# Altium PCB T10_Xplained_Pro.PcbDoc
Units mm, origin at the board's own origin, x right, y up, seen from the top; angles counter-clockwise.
Board outline 71.5 x 89.25 mm, 2 copper layers (Top Layer, Bottom Layer), stack 0.325 mm thick; 61 components, 52 nets, 281 pads, 100 vias.
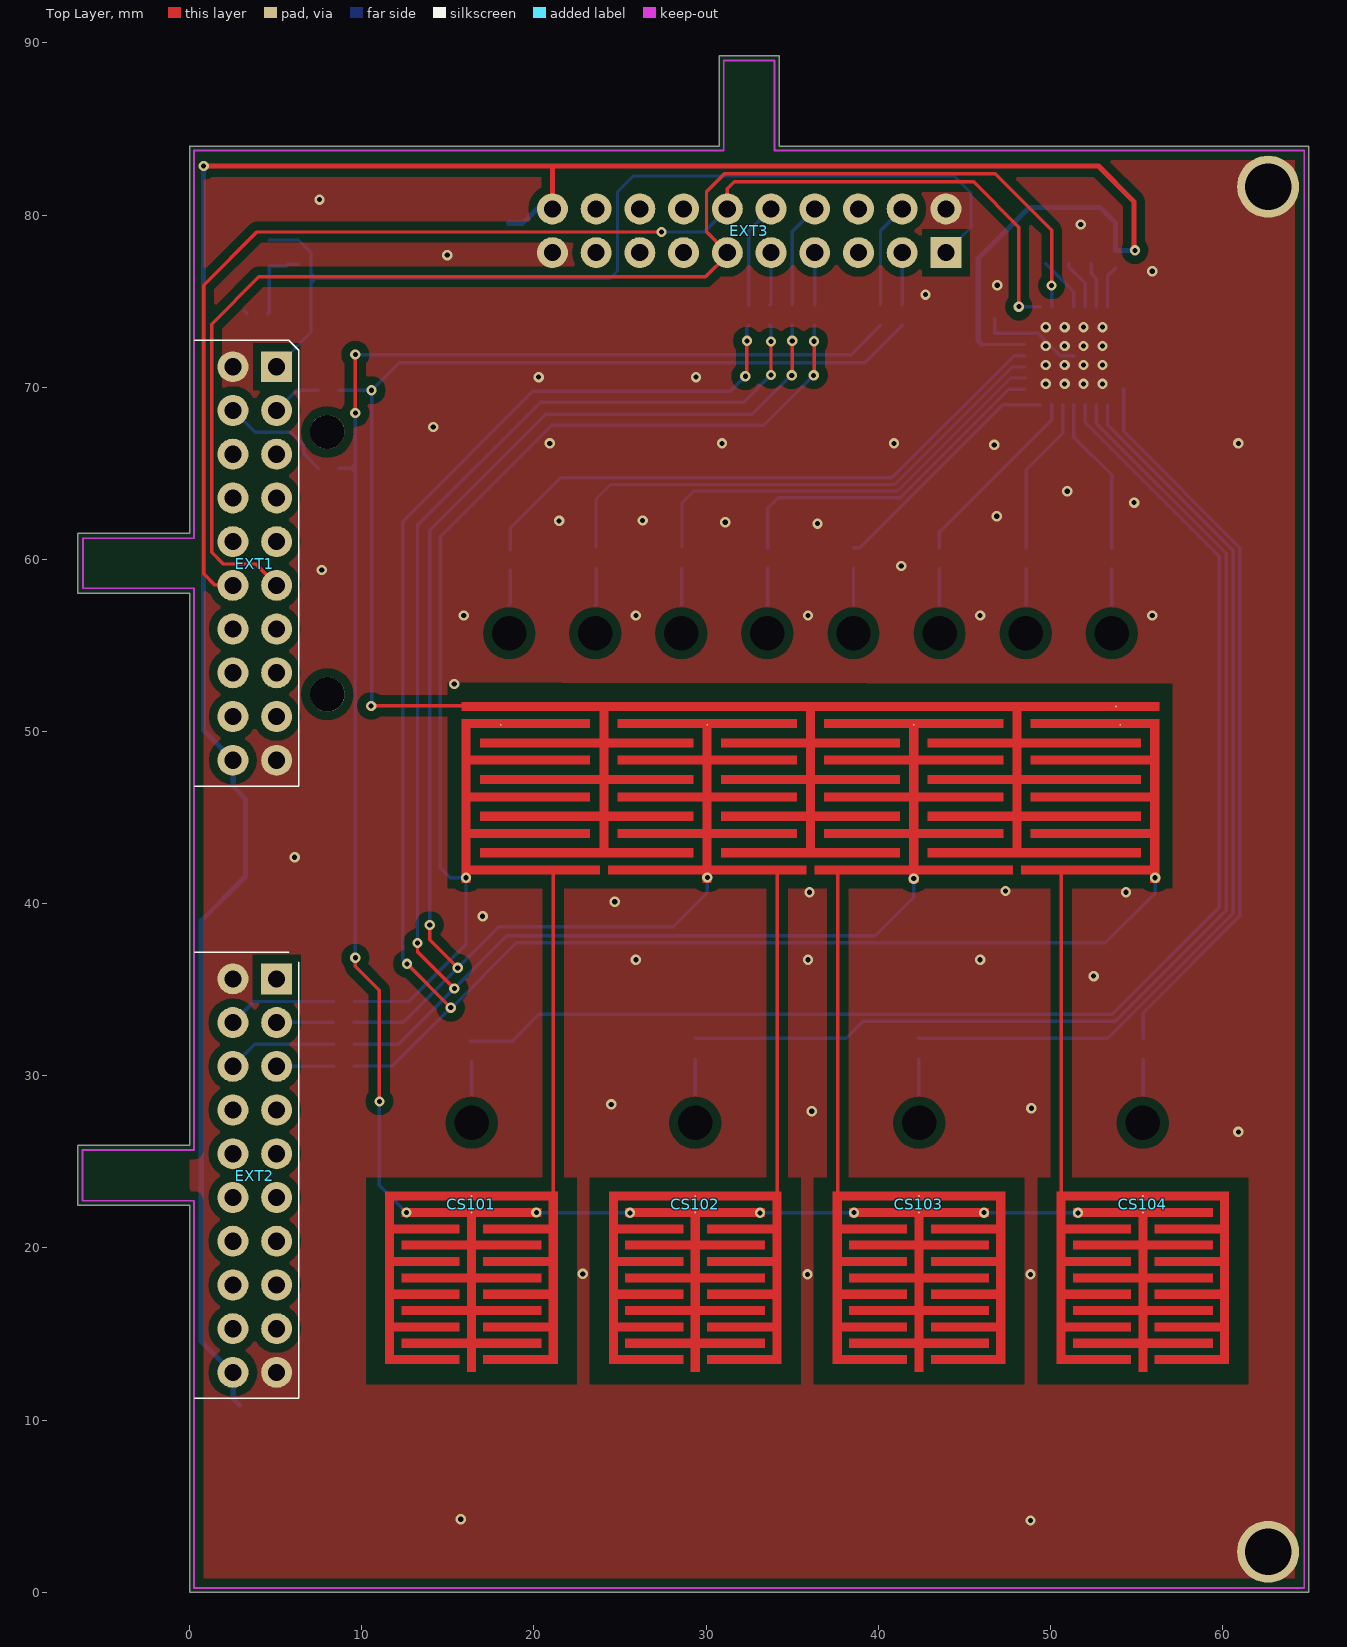
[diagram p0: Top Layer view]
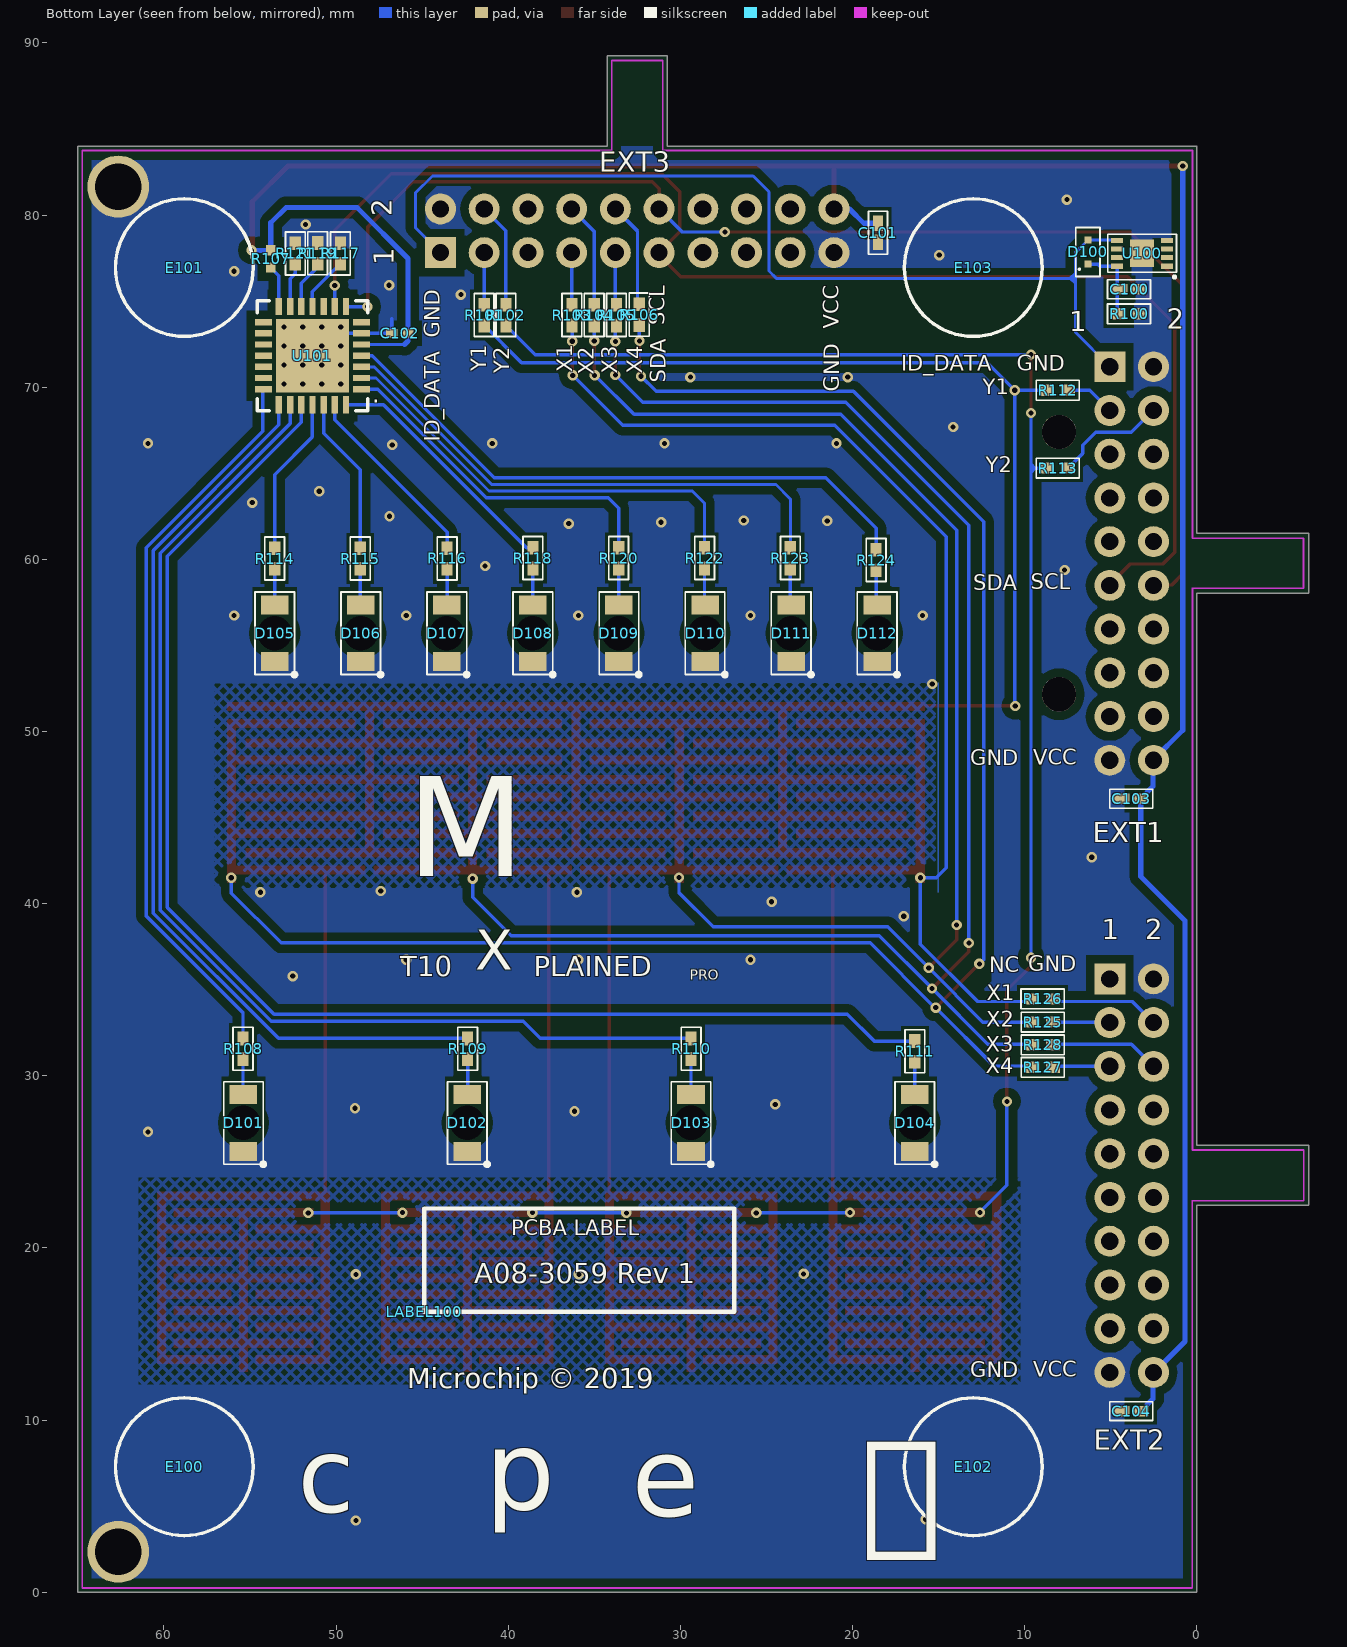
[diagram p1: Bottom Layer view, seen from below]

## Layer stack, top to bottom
Top Solder: solder mask 0.0102, Solder Resist, Dk 3.5
Top Layer: signal copper 0.0356
Dielectric 1: core 0.254, FR-4, Dk 4.2
Bottom Layer: signal copper 0.0356
Solder Side: solder mask 0.0102, Solder Resist, Dk 3.5

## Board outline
0,0 0,22.47 -6.5,22.47 -6.5,25.97 0,25.97 0,58.03 -6.5,58.03 -6.5,61.53 0,61.53 0.001,61.531 0.001,84.001 0,84 30.751,84 30.751,89.254 34.251,89.254 34.251,84 65,84 65,0

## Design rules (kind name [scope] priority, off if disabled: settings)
AcuteAngle [All] p1: minimum=8.50000000000000E+0001 checktracksonly=TRUE
AssemblyTestPointUsage [All] p1: allowmultiple=TRUE
AssemblyTestpoint [All] p1: testpointundercomponent=TRUE minsize=0.55 maxsize=2 preferedsize=0.8 minholesize=0 maxholesize=1 preferedholesize=0.25 testpointgrid=0.025 usegrid=FALSE gridtolerance=0 allowsidebottom=TRUE minspacing=1.27 compbodyclearance=0.127
Clearance Clearance_poly [InPolygon] p1: gap=0.5 ignorepadtopadclearanceinfootprint=FALSE except(0: Arc-Hole Track-Hole SMDPad-Hole THPad-Hole Via-Hole Fill-Hole Poly-Hole Region-Hole Text-Hole)
Clearance Clearance_LED [HasFootprint('AP4-00115')] p2: gap=0.05 ignorepadtopadclearanceinfootprint=FALSE except(0: Arc-Hole Track-Hole SMDPad-Hole THPad-Hole Via-Hole Fill-Hole Poly-Hole Region-Hole Text-Hole)
Clearance Clearance_1 [All] p3: gap=0.2 ignorepadtopadclearanceinfootprint=FALSE except(0: Arc-Hole Track-Hole SMDPad-Hole THPad-Hole Via-Hole Fill-Hole Poly-Hole Region-Hole Text-Hole)
ComponentClearance ComponentClearance_NoBOM [IsNoBOMComponent] p1: gap=0 collisioncheckmode=3 verticalgap=0 showdistances=FALSE
ComponentClearance [All] p2: gap=0.254 collisioncheckmode=3 verticalgap=0.254 showdistances=FALSE
DiffPairsRouting [All] p1: maxlimit=0.3 minlimit=0.15 mostfreqgap=0.2 toplayer_minwidth=0.381 toplayer_maxwidth=0.381 toplayer_prefwidth=0.381 bottomlayer_minwidth=0.381 bottomlayer_maxwidth=0.381 bottomlayer_prefwidth=0.381 maxuncoupledlength=20
FabricationTestPointUsage TestPointUsage [All] p1: valid=0 allowmultiple=TRUE
FabricationTestpoint Testpoint [All] p1: side=2 testpointundercomponent=TRUE minsize=0.55 maxsize=2 preferedsize=0.8 minholesize=0 maxholesize=1 preferedholesize=0.25 testpointgrid=0 allowsidebottom=TRUE usegrid=FALSE gridtolerance=0 minspacing=1.27 compbodyclearance=0.127
HoleSize [All] p1: absolutevalues=TRUE maxlimit=10 minlimit=0.2 maxpercent=80.000 minpercent=20.000
HoleToHoleClearance [All] p1: gap=0.45 allowstackedmicrovias=TRUE
MinimumAnnularRing [All] p1: minimumring=0.1
MinimumSolderMaskSliver [All] p1: minsoldermaskwidth=0.1
PasteMaskExpansion [All] p1: expansion=0.05
PlaneClearance [All] p1: clearance=0.3
PlaneConnect PlaneConnect_VIA [IsVia] p1: planeconnectstyle=Direct reliefexpansion=0.508 reliefentries=4 reliefconductorwidth=0.254 reliefairgap=0.254
PlaneConnect [All] p2: planeconnectstyle=Relief reliefexpansion=0.508 reliefentries=4 reliefconductorwidth=0.254 reliefairgap=0.254
PolygonConnect PolygonConnect_GND [HasPad('Free-666')] p1: connectstyle=Direct reliefconductorwidth=0.254 reliefentries=4 polygonreliefangle="90 Angle" airgapwidth=0.254
PolygonConnect PolygonConnect_VIA [IsVia] p2: connectstyle=Direct reliefconductorwidth=0.254 reliefentries=4 polygonreliefangle="90 Angle" airgapwidth=0.254
PolygonConnect [All] p3: connectstyle=Direct reliefconductorwidth=0.254 reliefentries=4 polygonreliefangle="90 Angle" airgapwidth=0.254
RoutingVias [All] p1: holewidth=0.3 width=0.6 viastyle="Through Hole" minholewidth=0.3 minwidth=0.6 maxholewidth=0.3 maxwidth=0.6
SMDNeckDown [All] p1: percent=70.000
SilkToSilkClearance SilkToSilkClearance_Text [IsText vs IsText] p1: silktosilkclearance=0
SilkToSilkClearance [All] p2: silktosilkclearance=0.01
SilkToSolderMaskClearance SilkscreenOverComponentPads [IsPad] p1: minsilkscreentomaskgap=0.1 clearancetoexposedcopper=TRUE
SolderMaskExpansion SolderMaskTenting [IsVia AND NOT (IsFabTestpoint OR IsAssyTestpoint)] p1: expansion=-1
SolderMaskExpansion [All] p2: expansion=0.05
ViasUnderSMD [All] p1: allowed=FALSE
Width [All] p1: maxlimit=0.3 minlimit=0.175 preferedwidth=0.2
16 further rules are at their usual default settings.

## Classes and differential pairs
component class T10_Xplained_Pro_TopLevel: E100 E101 E102 E103 FIXTURE100 LABEL100 PCB100 PCBADOC100 TEST100 TESTDOC100
component class T10_Xplained_Pro: C100 C101 C102 C103 C104 CS101 CS102 CS103 CS104 D100 D101 D102 D103 D104 D105 D106 D107 D108 D109 D110 D111 D112 EXT1 EXT2 EXT3 R100 R101 R102 R103 R104 R105 R106 R107 R108 R109 R110 R111 R112 R113 R114 R115 R116 R117 R118 R119 R120 R121 R122 R123 R124 R125 R126 R127 R128 U100 U101

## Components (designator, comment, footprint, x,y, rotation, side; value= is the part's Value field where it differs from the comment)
C100 "Recommended by Escatec. No datasheet available yet." AP1-00001 3.931,75.698 r180 bottom value=4.7uF
C101 "" AP1-00001 18.518,78.972 r270 bottom value=4.7uF
C102 "" AP1-00053 46.288,73.129 r0 bottom value=100n
C103 "" AP1-00001 3.8,46.095 r0 bottom value=4.7uF
C104 "" AP1-00001 3.8,10.52 r0 bottom value=4.7uF
CS101 "QMatrix Button 1" ? 16.368,18.261 r0 top
CS102 "QMatrix Button 1" ? 29.368,18.261 r0 top
CS103 "QMatrix Button 1" ? 42.368,18.261 r0 top
CS104 "QMatrix Button 1" ? 55.376,18.261 r0 top
D100 "Farnell# 1615809" AP4-00036 6.319,77.857 r90 bottom value=BAT54XV2T1G
D101 "LED_21" AP4-00115 55.376,27.261 r270 bottom value=LTST-C250KRKT
D102 "LED_21" AP4-00115 42.376,27.261 r270 bottom value=LTST-C250KRKT
D103 "LED_21" AP4-00115 29.376,27.261 r270 bottom value=LTST-C250KRKT
D104 "LED_21" AP4-00115 16.376,27.261 r270 bottom value=LTST-C250KRKT
D105 "LED_21" AP4-00115 53.562,55.707 r270 bottom value=LTST-C250KRKT
D106 "LED_21" AP4-00115 48.562,55.707 r270 bottom value=LTST-C250KRKT
D107 "LED_21" AP4-00115 43.562,55.707 r270 bottom value=LTST-C250KRKT
D108 "LED_21" AP4-00115 38.562,55.707 r270 bottom value=LTST-C250KRKT
D109 "LED_21" AP4-00115 33.562,55.707 r270 bottom value=LTST-C250KRKT
D110 "LED_21" AP4-00115 28.562,55.707 r270 bottom value=LTST-C250KRKT
D111 "LED_21" AP4-00115 23.562,55.707 r270 bottom value=LTST-C250KRKT
D112 "LED_21" AP4-00115 18.562,55.707 r270 bottom value=LTST-C250KRKT
E100 "" AP8-00192 58.811,7.29 r180 bottom value=SJ-5076
E101 "" AP8-00192 58.811,76.951 r180 bottom value=SJ-5076
E102 "" AP8-00192 12.979,7.29 r180 bottom value=SJ-5076
E103 "" AP8-00192 12.979,76.951 r180 bottom value=SJ-5076
EXT1 "" AP8-00621 3.78,59.76 r90 top locked value=TF201-2*10RGF-W2-NF
EXT2 "" AP8-00621 3.78,24.2 r90 top locked value=TF201-2*10RGF-W2-NF
EXT3 "" AP8-00621 32.501,79.089 r0 top value=TF201-2*10RGF-W2-NF
LABEL100 "" AP8-00317 44.87,16.293 r180 bottom value="Label PCBA"
R100 "R2" AP2-00000 3.931,74.265 r0 bottom value=100k
R101 "R2" AP2-00000 41.391,74.193 r270 bottom value=1k
R102 "R2" AP2-00000 40.132,74.193 r90 bottom value=1k
R103 "R2" AP2-00000 36.297,74.193 r270 bottom value=1k
R104 "R2" AP2-00000 35.001,74.193 r90 bottom value=1k
R105 "R2" AP2-00000 33.706,74.193 r270 bottom value=1k
R106 "R2" AP2-00000 32.385,74.219 r90 bottom value=1k
R107 "" AP2-00011 53.786,77.451 r90 bottom value=1k
R108 "R2" AP2-00000 55.402,31.573 r270 bottom value=330R
R109 "R2" AP2-00000 42.352,31.573 r270 bottom value=330R
R110 "R2" AP2-00000 29.376,31.573 r270 bottom value=330R
R111 "R2" AP2-00000 16.376,31.419 r270 bottom value=330R
R112 "R2" AP2-00000 8.077,69.825 r0 bottom value=1k
R113 "R2" AP2-00000 8.077,65.303 r180 bottom value=1k
R114 "R2" AP2-00000 53.562,60.05 r270 bottom value=330R
R115 "R2" AP2-00000 48.591,60.05 r270 bottom value=330R
R116 "R2" AP2-00000 43.547,60.052 r270 bottom value=330R
R117 "R2" AP2-00000 49.743,77.769 r270 bottom value=0R
R118 "R2" AP2-00000 38.562,60.077 r270 bottom value=330R
R119 "R2" AP2-00000 51.063,77.777 r270 bottom value=0R
R120 "R2" AP2-00000 33.577,60.077 r270 bottom value=330R
R121 "R2" AP2-00000 52.364,77.769 r270 bottom value=0R
R122 "R2" AP2-00000 28.592,60.077 r270 bottom value=330R
R123 "R2" AP2-00000 23.607,60.077 r270 bottom value=330R
R124 "R2" AP2-00000 18.622,59.962 r270 bottom value=330R
R125 "R2" AP2-00000 8.941,33.122 r0 bottom value=1k
R126 "R2" AP2-00000 8.95,34.468 r180 bottom value=1k
R127 "R2" AP2-00000 8.941,30.494 r0 bottom value=1k
R128 "R2" AP2-00000 8.941,31.801 r180 bottom value=1k
U100 "ATSHA204A-SWI" AP6-00409 3.169,77.781 r0 bottom value="ATSHA204 SWI UDFN8"
U101 "MCP23017-E_ML" AP6-00497 51.368,71.833 r0 bottom value=MCP23017

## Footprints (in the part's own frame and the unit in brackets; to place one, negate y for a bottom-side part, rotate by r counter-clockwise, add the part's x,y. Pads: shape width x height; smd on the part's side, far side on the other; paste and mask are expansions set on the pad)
AP1-00001 [mm] "Standard 0402 SMD capacitor footprint"
  rect 0.9x0.6 smd: 1(-0.55,0) 2(0.55,0)
  silkscreen extent -1.25,-0.55 1.25,0.55, body extent -0.5,-0.3 0.5,0.3, height 0.2
AP1-00053 [mm] "Chip Capacitor, 2-Leads, Body 1.0x0.5mm, IPC High Density"
  rect 0.65x0.5 smd: 1(-0.475,0) 2(0.475,0)
  body extent -0.5,-0.3 0.5,0.3, height 0.2
AP2-00000 [mm] "Standard 0402 SMD resistor footprint"
  rect 0.8x0.65 smd: 1(-0.6,0) 2(0.6,0)
  silkscreen extent -1.25,-0.58 1.25,0.58, body extent -0.5,-0.3 0.5,0.3, height 0.2
AP2-00011 [mm] "Chip Resistor, 2-Leads, Body 1,0x0,5mm, IPC High Density"
  rect 0.6x0.55 smd: 1(-0.5,0) 2(0.5,0)
  body extent -0.5,-0.3 0.5,0.3, height 0.2
AP4-00036 [mm] "Molded Diode, 2-Leads, Body 1,2x0,8mm, IPC Medium Density"
  rect 0.4x0.4 smd: 1(-0.7,0) 2(0.7,0)
  silkscreen extent -1.42,-0.7 1.43,0.7, body extent -0.8,-0.4 0.8,0.4, height 0.7
AP4-00115 [mm] "3.2x1.6mm, 1305, Reverse mount SMD LED"
  round 0 hole 2 unplated: 0(0,0)
  rect 1.1x1.6 smd: 1(-1.65,0) 2(1.65,0)
  silkscreen extent -2.4,-1.15 2.5,1.25, body extent -1.6,-0.8 1.6,0.8, height 0.29
AP6-00409 [mm]
  rect 0.7x0.3 smd mask-1: 1(-1.45,0.75) 2(-1.45,0.25) 3(-1.45,-0.25) 4(-1.45,-0.75) 5(1.45,-0.75) 6(1.45,-0.25) 7(1.45,0.25) 8(1.45,0.75)
  rect 1.4x1.6 smd paste-0.025 mask+0.075: 9(0,0)
  silkscreen extent -2,-1.1 2,1.45, body extent -1.55,-1.05 1.55,1.05, height 0.6
AP6-00497 [mm] "QFN, 28-Leads, Body 6x6mm (max), Pitch 0.65mm, IPC Medium Density"
  rect 1x0.37 smd: 1(-2.85,1.95) 2(-2.85,1.3) 3(-2.85,0.65) 4(-2.85,0) 5(-2.85,-0.65) 6(-2.85,-1.3) 7(-2.85,-1.95) 15(2.85,-1.95) 16(2.85,-1.3) 17(2.85,-0.65) 18(2.85,0) 19(2.85,0.65) 20(2.85,1.3) 21(2.85,1.95)
  rect 0.37x1 smd: 8(-1.95,-2.85) 9(-1.3,-2.85) 10(-0.65,-2.85) 11(0,-2.85) 12(0.65,-2.85) 13(1.3,-2.85) 14(1.95,-2.85) 22(1.95,2.85) 23(1.3,2.85) 24(0.65,2.85) 25(0,2.85) 26(-0.65,2.85) 27(-1.3,2.85) 28(-1.95,2.85)
  rect 4.25x4.25 smd: 29(0,0)
  silkscreen extent -3.2,-3.2 3.2,3.2, body extent -3,-3 3,3, height 1.02
AP8-00192 [mm]
  silkscreen extent -4,-4 4,4, body extent -4,-4 4,4, height 2.79
AP8-00317 [mm] "Placement area for 18x6mm sticker"
  silkscreen extent 0,0 18,6
AP8-00621 [mm] "2x5 Receptacle THM, Right Angle. No Guide. 2.54mm pitch. Length 13.2mm, width 5.0mm, height 5mm"
  rect 1.8x1.8 hole 1: 1(11.43,-1.27)
  round 1.8 hole 1: 2(11.43,1.27) 3(8.89,-1.27) 4(8.89,1.27) 5(6.35,-1.27) 6(6.35,1.27) 7(3.81,-1.27) 8(3.81,1.27) 9(1.27,-1.27) 10(1.27,1.27) 11(-1.27,-1.27) 12(-1.27,1.27) 13(-3.81,-1.27) 14(-3.81,1.27) 15(-6.35,-1.27) 16(-6.35,1.27) 17(-8.89,-1.27) 18(-8.89,1.27) 19(-11.43,-1.27) 20(-11.43,1.27)
  rect 2.1x2.1 on Top Paste: 19(-11.43,-1.27) 19(-11.43,1.27) 19(-8.89,-1.27) 19(-8.89,1.27) 19(-6.35,-1.27) 19(-6.35,1.27) 19(-3.81,-1.27) 19(-3.81,1.27) 19(-1.27,-1.27) 19(-1.27,1.27) 19(1.27,-1.27) 19(1.27,1.27) 19(3.81,-1.27) 19(3.81,1.27) 19(6.35,-1.27) 19(6.35,1.27) 19(8.89,-1.27) 19(8.89,1.27) 19(11.43,-1.27) 19(11.43,1.27)
  body extent -12.95,-1.47 12.95,11.3, height 4.98
? [mm]
  round 0.1 smd paste-0.05: X(0,4.75) Y(0,3.8)
  Top Layer region: -0.7,-5 -5,-5 -5,5 5,5 5,-5 0.7,-5 0.7,-4.5 4.5,-4.5 4.5,-3.1 0.7,-3.1 0.7,-2.6 4.5,-2.6 4.5,-1.2 0.7,-1.2 0.7,-0.7 4.5,-0.7 4.5,0.7 0.7,0.7 0.7,1.2 4.5,1.2 4.5,2.6 0.7,2.6 0.7,3.1 4.5,3.1 4.5,4.5 -4.5,4.5 -4.5,3.1 -0.7,3.1 -0.7,2.6 -4.5,2.6 -4.5,1.2 -0.7,1.2 -0.7,0.7 -4.5,0.7 -4.5,-0.7 -0.7,-0.7 -0.7,-1.2 -4.5,-1.2 -4.5,-2.6 -0.7,-2.6 -0.7,-3.1 -4.5,-3.1 -4.5,-4.5 -0.7,-4.5 -0.7,-5
  Top Layer region: -0.25,-5.45 -0.25,-4.05 -4.05,-4.05 -4.05,-3.55 -0.25,-3.55 -0.25,-2.15 -4.05,-2.15 -4.05,-1.65 -0.25,-1.65 -0.25,-0.25 -4.05,-0.25 -4.05,0.25 -0.25,0.25 -0.25,1.65 -4.05,1.65 -4.05,2.15 -0.25,2.15 -0.25,3.55 -4.05,3.55 -4.05,4.05 -0.25,4.05 0.25,4.05 4.05,4.05 4.05,3.55 0.25,3.55 0.25,2.15 4.05,2.15 4.05,1.65 0.25,1.65 0.25,0.25 4.05,0.25 4.05,-0.25 0.25,-0.25 0.25,-1.65 4.05,-1.65 4.05,-2.15 0.25,-2.15 0.25,-3.55 4.05,-3.55 4.05,-4.05 0.25,-4.05 0.25,-5.45 -0.25,-5.45

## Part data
C100 C101 C103 C104: library part A01-0347, "Ceramic capacitor, SMD 0402, X5R, 6.3V, +/-20% (de33687)", Manufacturer=Murata, MPN=GRM155R60J475ME87D, TemperatureRange="-55°C to +85°C", Tolerance=+-20%
C102: library part A01-0246, "Ceramic capacitor, SMD 0402, X7R, 16V, +/-10%", Manufacturer=Kemet, MPN=C0402C104K4RACTU, TemperatureRange="-55 - +125 deg C", Tolerance="16V, +/-10%"
CS101 CS102 CS103 CS104: library part QMatrixButton, "QMatrix Button"
D100: library part A04-0049, "Schottky diode, If:200mA, Vf:0.35V, Vrrm:30V, SOD-523", Manufacturer="ON Semiconductor", MPN=BAT54XV2T1G, TemperatureRange="-55°C to +125°C"
D101 D102 D103 D104 D105 D106 D107 D108 D109 D110 D111 D112: library part A10-0204, "LED, SMD, RED, 3.2x1.2mm, reverse mount"
E100 E101 E102 E103: library part A08-0053, "2.8mm adhesive feet,diam 8.0mm", Manufacturer=3M, MPN=SJ-5076
EXT1 EXT2 EXT3: library part A08-1512, "2x10, female pin header receptable, right-angled, 2.54mm pitch, THM, Pin In Paste", Manufacturer="Pro-data International Corp", MPN=F201-2*10RGF-W2-NF
LABEL100: library part A09-0611, "PCBA identification label PP Top White Gloss", Manufacturer="ACT Logimark AS", MPN=505462
R100: library part A02-0260, "Thick film resistor, SMD 0402, 1/16W, 1%", TemperatureRange="-55 - +125 deg C", Tolerance="1 %"
R101 R102 R103 R104 R105 R106 R107 R112 R113 R125 R126 R127 R128: library part A02-0212, "Thick film resistor, SMD 0402, 1/16W, 1%", TemperatureRange="-55 - +125 deg C", Tolerance="1 %"
R108 R109 R110 R111 R114 R115 R116 R118 R120 R122 R123 R124: library part A02-0200, "Thick film resistor, SMD 0402, 1/16W, 1%", Manufacturer=ASJ, MPN=CR10-3300-FK, TemperatureRange="-55 - +125 deg C", Tolerance="1 %"
R117 R119 R121: library part A02-0163, "RES 0.0 OHM 1/16W 0402 SMD", Manufacturer=(n/a), MPN=RMCF0402ZT0R00, TemperatureRange="-55 - +125 deg C", Tolerance="1 %"
U100: library part A06-1276, "ATSHA204 with 1-wire interface and UDFN8 package", Manufacturer=ATMEL, MPN=ATSHA204A-MAHCZ-T
U101: library part A06-1534, "16-Bit I/O Expander with I2C interface, 28-Lead QFN", Manufacturer="Microchip Technology Inc", MPN=MCP23017-E/ML, TemperatureRange="-40°C to +125°C"

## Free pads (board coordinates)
  round 2 hole 2 unplated: 2(8,67.4) 3(8,52.16)
  round 3.6 hole 2.7 paste-2.6: 666(62.65,2.35) 666(62.65,81.65)
  round 0.1 smd paste-0.05: x1(18.062,50.397) x2(30.062,50.397) x3(42.062,50.397) x4(54.062,50.397) Y(53.812,51.457)

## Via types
v1: diameter 0.6, hole 0.3, Top Layer to Bottom Layer, 70 vias
v2: diameter 0.6, hole 0.3, Top Layer to Bottom Layer, tented both sides, 30 vias

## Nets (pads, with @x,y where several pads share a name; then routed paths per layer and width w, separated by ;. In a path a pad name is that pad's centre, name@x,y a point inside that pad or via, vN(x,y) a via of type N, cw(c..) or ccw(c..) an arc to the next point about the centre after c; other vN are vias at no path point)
GND: C100.2 C101.2 C102.2 C103.2 C104.2 D101.2 D102.2 D103.2 D104.2 D105.2 D106.2 D107.2 D108.2 D109.2 D110.2 D111.2 D112.2 EXT1.2 EXT1.19@5.05,48.33 EXT2.2 EXT2.19@5.05,12.77 EXT3.2 EXT3.19@21.071,77.819 pad.666 R100.1 R117.1 R119.1 R121.1 U100.4 U100.9 U101.6 U101.29 | length 6.2
  Bottom Layer w0.2: R100.1@3.169,74.427 R100.1 ; C102.2 46.763,73.988
  Bottom Layer w0.203: C102.2 48.514,73.129 U101.6 49.28,73.133 50.58,71.833 U101.29
  other v1: 48.844,4.166 15.748,4.242 35.89,18.466 48.844,18.466 22.835,18.491 36.14,27.94 48.895,28.118 24.486,28.341 52.512,35.789 17.018,39.271 24.695,40.107 36.008,40.665 54.393,40.665 47.396,40.74 6.096,42.697 15.367,52.756 7.671,59.385 41.337,59.614 36.474,62.078 31.115,62.154 21.463,62.234 26.314,62.255 46.888,62.509 54.866,63.297 50.978,63.955 46.736,66.65 14.148,67.691 20.269,70.587 29.413,70.587 42.748,75.381 46.915,75.921 14.961,77.673 51.765,79.451 7.544,80.899
  other v2: 60.92,26.74 25.92,36.74 35.92,36.74 45.92,36.74 15.92,56.74 25.92,56.74 35.92,56.74 45.92,56.74 55.92,56.74 20.92,66.74 30.92,66.74 40.92,66.74 60.92,66.74 49.728,70.193 50.828,70.193 51.928,70.193 53.028,70.193 49.728,71.293 50.828,71.293 51.928,71.293 53.028,71.293 49.728,72.393 50.828,72.393 51.928,72.393 53.028,72.393 49.728,73.493 50.828,73.493 51.928,73.493 53.028,73.493 55.92,76.74
ID_DATA: D100.2 EXT1.1 EXT3.1 U100.5 | length 59.3
  Bottom Layer w0.175: U100.5 4.632,78.544 6.306,78.544 D100.2 7.034,77.841 7.034,76.633 ; EXT1.1@5.07,71.21 7.034,73.174 7.034,76.026 ; 7.034,76.407 7.112,76.329 7.338,76.329 ; 7.186,76.178 7.186,76.333 7.26,76.407 ; EXT3.1 45.39,79.277 45.39,81.28 44.398,82.272 25.767,82.272 24.847,81.352 24.847,76.752 24.424,76.329 7.338,76.329 ; 7.034,76.026 7.338,76.329 ; 7.034,76.026 7.034,76.633 ; 7.034,76.633 7.338,76.329
NetC100_1: C100.1 D100.1 R100.2 U100.8 | length 4.6
  Bottom Layer w0.2: R100.2 4.619,74.353 U100.8 5.619,77.031 5.745,77.157 D100.1
NetD101_1: D101.1 R108.2 | length 2.1
  Bottom Layer w0.2: D101.1@55.402,28.911 R108.2
NetD102_1: D102.1 R109.2 | length 2.1
  Bottom Layer w0.2: D102.1@42.352,28.911 R109.2
NetD103_1: D103.1 R110.2 | length 2.1
  Bottom Layer w0.2: D103.1 R110.2
NetD104_1: D104.1 R111.2 | length 1.9
  Bottom Layer w0.2: D104.1 R111.2
NetD105_1: D105.1 R114.2 | length 2.1
  Bottom Layer w0.2: D105.1 R114.2
NetD106_1: D106.1 R115.2 | length 2.1
  Bottom Layer w0.2: D106.1 48.591,57.386 R115.2
NetD107_1: D107.1 R116.2 | length 2.1
  Bottom Layer w0.2: R116.2 43.547,57.372 D107.1
NetD108_1: D108.1 R118.2 | length 2.1
  Bottom Layer w0.2: D108.1 R118.2
NetD109_1: D109.1 R120.2 | length 2.1
  Bottom Layer w0.2: D109.1 33.577,57.372 R120.2
NetD110_1: D110.1 R122.2 | length 2.1
  Bottom Layer w0.2: D110.1 28.592,57.387 R122.2
NetD111_1: D111.1 R123.2 | length 2.1
  Bottom Layer w0.2: D111.1 23.607,57.402 R123.2
NetD112_1: D112.1 R124.2 | length 2
  Bottom Layer w0.2: D112.1 18.622,57.417 R124.2
NetEXT1_3: EXT1.3 R112.1 | length 2.9
  Bottom Layer w0.2: EXT1.3@5.07,68.67 6.225,69.825 R112.1
NetEXT1_4: EXT1.4 R113.2 | length 6.6
  Bottom Layer w0.2: EXT1.4@2.53,68.67 3.814,67.386 5.867,67.386 6.629,66.624 6.629,66.151 R113.2
NetEXT2_3: EXT2.3 R125.1 | length 3.8
  Top Layer w0.2: EXT2.3@5.07,33.11 EXT2.3@5.585,33.11
  Bottom Layer w0.2: EXT2.3@5.07,33.11 5.082,33.122 R125.1
NetEXT2_4: EXT2.4 R126.2 | length 6.3
  Bottom Layer w0.2: EXT2.4@2.53,33.11 3.735,34.315 R126.2@8.366,34.315
NetEXT2_5: EXT2.5 R127.1 | length 4.5
  Top Layer w0.2: EXT2.5@5.07,30.57 EXT2.5@5.792,30.57
  Bottom Layer w0.2: EXT2.5@5.578,30.57 5.07,30.57 5.084,30.556 R127.1@8.366,30.556
NetEXT2_6: EXT2.6 R128.2 | length 6.4
  Bottom Layer w0.2: EXT2.6@2.53,30.57 3.786,31.826 R128.2@8.366,31.826
NetEXT3_3: EXT3.3 R101.1 | length 3
  Bottom Layer w0.2: R101.1 EXT3.3
NetEXT3_4: EXT3.4 R102.2 | length 6.1
  Bottom Layer w0.2: R102.2 40.132,79.1 EXT3.4
NetEXT3_7: EXT3.7 R103.1 | length 3.6
  Top Layer w0.2: EXT3.7 36.462,77.669 36.347,77.554 EXT3.7@36.468,77.432
  Bottom Layer w0.2: R103.1 36.311,74.808 EXT3.7
NetEXT3_8: EXT3.8 R104.2 | length 6.1
  Bottom Layer w0.2: R104.2 35.001,79.049 EXT3.8
NetEXT3_9: EXT3.9 R105.1 | length 3.1
  Bottom Layer w0.2: R105.1 33.771,74.859 EXT3.9
NetEXT3_10: EXT3.10 R106.2 | length 6.1
  Bottom Layer w0.2: R106.2@32.487,74.768 32.487,79.074 EXT3.10
NetR107_1: R107.1 U101.14 | length 2.5
  Bottom Layer w0.2: U101.14 53.318,76.483 R107.1
NetR108_1: R108.1 U101.21 | length 42.9
  Bottom Layer w0.2: U101.21 54.254,69.919 54.254,67.438 61.012,60.681 61.012,39.281 55.402,33.671 R108.1
NetR109_1: R109.1 U101.22 | length 53.9
  Bottom Layer w0.2: R109.1@42.312,32.173 53.338,32.173 60.612,39.446 60.612,60.515 53.318,67.808 U101.22
NetR110_1: R110.1 U101.23 | length 66.4
  Bottom Layer w0.2: R110.1 38.138,32.173 39.132,33.167 53.767,33.167 60.212,39.612 60.212,60.349 52.668,67.893 U101.23
NetR111_1: R111.1 U101.24 | length 79.2
  Bottom Layer w0.2: R111.1@16.286,32.019 18.741,32.019 20.289,33.567 53.601,33.567 59.812,39.778 59.812,60.184 52.018,67.977 U101.24
NetR117_2: R117.2 U101.11 | length 3.2
  Bottom Layer w0.2: R117.2 51.368,75.544 U101.11
NetR119_2: R119.2 U101.12 | length 2.9
  Bottom Layer w0.2: R119.2 51.063,76.985 52.018,76.03 U101.12
NetR121_2: R121.2 U101.13 | length 2.6
  Bottom Layer w0.2: R121.2 52.364,76.605 52.668,76.3 U101.13
SCL: EXT1.12 EXT3.12 U101.8 | length 76.2
  Top Layer w0.2: EXT1.12@2.53,58.51 1.458,58.51 0.812,59.157 0.812,75.936 3.895,79.019 v1(27.409,79.019) ; EXT3.12 31.231,81.527 31.632,81.927 45.547,81.927 48.168,79.305 v1(48.168,74.682)
  Bottom Layer w0.2: v1(27.409,79.019) 29.891,79.019 EXT3.12 ; v1(48.168,74.682) 48.17,74.683 U101.8
SDA: EXT1.11 EXT3.11 U101.9 | length 79.9
  Top Layer w0.2: EXT1.11@5.07,58.51 3.848,59.732 1.962,59.732 1.272,60.422 1.272,73.656 4.022,76.407 29.966,76.407 31.231,77.672 EXT3.11 30.022,79.029 30.022,81.352 31.067,82.397 46.801,82.397 50.068,79.13 v1(50.068,75.91)
  Bottom Layer w0.2: U101.9 v1(50.068,75.91)
SLIDER_1: R124.1 U101.4 | length 35.3
  Bottom Layer w0.2: R124.1 18.622,61.802 21.552,64.732 40.797,64.732 47.899,71.833 U101.4
SLIDER_2: R123.1 U101.3 | length 30.9
  Bottom Layer w0.175: R123.1 23.607,63.51 24.441,64.344 40.958,64.344 47.797,71.183 U101.3
SLIDER_3: R122.1 U101.2 | length 25.5
  Bottom Layer w0.175: R122.1 28.592,63.263 29.298,63.969 41.113,63.969 47.677,70.533 U101.2
SLIDER_4: R120.1 U101.1 | length 20.1
  Bottom Layer w0.2: R120.1 33.577,62.964 34.194,63.582 41.274,63.582 47.575,69.883 U101.1
SLIDER_5: R118.1 U101.28 | length 14.3
  Bottom Layer w0.2: R118.1 38.934,60.677 47.241,68.983 U101.28
SLIDER_6: R116.1 U101.27 | length 11
  Bottom Layer w0.2: R116.1 43.547,61.582 50.068,68.103 U101.27
SLIDER_7: R115.1 U101.26 | length 9.2
  Bottom Layer w0.2: R115.1 48.591,65.198 50.718,67.325 U101.26
SLIDER_8: R114.1 U101.25 | length 9.2
  Bottom Layer w0.2: U101.25 51.368,67.11 53.562,64.916 R114.1
VCC_TARGET: C101.1 C102.1 C103.1 C104.1 EXT1.20 EXT2.20 EXT3.20 R107.2 U101.5 | length 158
  Top Layer w0.3: v1(0.811,82.847) 52.791,82.847 54.862,80.777 54.862,78.001 v1(54.911,77.951) ; EXT3.20 21.071,82.847
  Bottom Layer w0.2: 46.024,72.483 U101.5
  Bottom Layer w0.3: v1(0.811,82.847) 0.811,50.069 2.53,48.35 2.53,46.815 C103.1 3.25,41.585 0.672,39.007 0.672,14.561 2.443,12.79 2.53,12.79 2.53,11.24 2.882,10.888 ; C101.1 19.337,79.522 20.174,80.359 EXT3.20 ; 46.024,72.483 45.813,72.694 C102.1 45.813,77.478 48.767,80.432 52.907,80.432 53.786,79.552 R107.2 v1(54.911,77.951)
X_1: CS101.X pad.x1 R103.2 R126.1 | length 80.4
  Top Layer w0.2: 21.057,22.809 21.133,22.885 21.133,41.986 ; v1@36.246,72.644 v1(36.271,72.669) ; v1@36.271,70.688 v1@36.271,72.644
  Bottom Layer w0.2: R126.1@9.566,34.315 12.725,34.315 16.053,37.643 v1(16.053,41.504) 15.137,41.504 14.554,42.087 14.554,61.314 21.033,67.793 33.35,67.793 v1(36.246,70.688) ; v1(36.271,72.669) 36.271,73.538 36.311,73.579 R103.2
X_2: CS102.X pad.x2 R104.1 R125.2 | length 97.3
  Top Layer w0.2: v1(13.945,38.76) 13.945,37.897 v1(15.57,36.271) ; 34.138,22.987 34.138,41.935 ; v1@34.9,70.637 v1@35.052,70.79 ; v1@35.001,70.79 v1(35.001,72.694)
  Bottom Layer w0.2: R125.2 12.421,33.122 v1(15.57,36.271) 17.958,38.659 28.092,38.659 30.074,40.64 v1(30.074,41.517) ; v1(13.945,38.76) 13.945,61.697 20.676,68.428 32.69,68.428 v1@34.9,70.637 ; R104.1 35.001,72.745 v1@35.052,72.694
  other v1: 34.976,70.688
X_3: CS103.X pad.x3 R105.2 R128.1 | length 111
  Top Layer w0.2: v1(13.233,37.719) 13.233,37.211 v1(15.375,35.07) ; v1(33.771,70.714) v1(33.771,72.659) ; 37.643,41.957 37.643,23.086 37.718,23.011 ; 47.092,42.037 47.117,42.012
  Bottom Layer w0.2: R128.1@9.566,31.826 12.131,31.826 v1(15.375,35.07) 18.43,38.125 39.827,38.125 42.062,40.361 v1(42.062,41.453) ; v1(13.233,37.719) 13.233,61.976 20.383,69.126 32.184,69.126 v1(33.771,70.714) ; R105.2 33.771,73.528 v1(33.771,72.659)
X_4: CS104.X pad.x4 R106.1 R127.2 | length 126.4
  Top Layer w0.2: v1(12.624,36.5) v1(15.164,33.96) ; v1(32.283,70.637) 32.372,70.726 v1(32.372,72.695) ; 50.622,22.936 50.622,41.957
  Bottom Layer w0.2: R127.2@9.541,30.57 11.774,30.57 v1(15.164,33.96) 15.215,33.96 18.974,37.719 53.188,37.719 56.083,40.615 v1(56.083,41.504) ; v1(12.624,36.5) 12.373,36.751 12.373,62.19 19.937,69.755 31.401,69.755 v1(32.283,70.637) ; v1(32.372,72.695) 32.372,73.453 R106.1@32.487,73.568
Y_1: pad.Y R101.2 R112.2 | length 58.6
  Top Layer w0.2: v1(10.541,51.486) 16.535,51.486
  Bottom Layer w0.2: R112.2 v1(10.566,69.825) ; v1(10.541,51.486) 10.566,51.511 v1(10.566,69.825) ; R101.2 39.223,71.425 12.167,71.425 v1(10.566,69.825)
Y_2: CS101.Y CS102.Y CS103.Y CS104.Y R102.1 R113.1 | length 100.3
  Top Layer w0.2: v1(9.627,36.855) 9.627,36.354 11.024,34.957 v1(11.024,28.51) ; v1(9.627,68.504) v1(9.627,71.898) ; 19.517,22.052 19.557,22.012
  Bottom Layer w0.2: R113.1 9.398,65.303 ; v1(9.627,36.855) 9.627,65.329 ; 9.627,65.075 9.398,65.303 ; 9.627,65.532 9.398,65.303 ; v1(9.627,68.504) 9.627,65.329 ; v1(9.627,71.898) 38.436,71.898 R102.1 ; v1(11.024,28.51) 11.024,23.63 v1(12.593,22.061) ; v1(20.142,22.061) 20.154,22.049 25.57,22.049 v1(25.582,22.037) ; v1(33.132,22.037) 33.138,22.043 38.586,22.043 v1(38.592,22.049) ; v1(46.142,22.049) 46.148,22.043 51.603,22.043 v1(51.609,22.037) ; 9.398,65.303 9.601,65.303 9.627,65.329
pads on no net: D101.0 D102.0 D103.0 D104.0 D105.0 D106.0 D107.0 D108.0 D109.0 D110.0 D111.0 D112.0 EXT1.5 EXT1.6 EXT1.7 EXT1.8 EXT1.9 EXT1.10 EXT1.13 EXT1.14 EXT1.15 EXT1.16 EXT1.17 EXT1.18 EXT1.19@2.51,48.33 EXT1.19@2.51,50.87 EXT1.19@2.51,53.41 EXT1.19@2.51,55.95 EXT1.19@2.51,58.49 EXT1.19@2.51,61.03 EXT1.19@2.51,63.57 EXT1.19@2.51,66.11 EXT1.19@2.51,68.65 EXT1.19@2.51,71.19 EXT1.19@5.05,48.33 EXT1.19@5.05,50.87 EXT1.19@5.05,53.41 EXT1.19@5.05,55.95 EXT1.19@5.05,58.49 EXT1.19@5.05,61.03 EXT1.19@5.05,63.57 EXT1.19@5.05,66.11 EXT1.19@5.05,68.65 EXT1.19@5.05,71.19 EXT2.1 EXT2.7 EXT2.8 EXT2.9 EXT2.10 EXT2.11 EXT2.12 EXT2.13 EXT2.14 EXT2.15 EXT2.16 EXT2.17 EXT2.18 EXT2.19@2.51,12.77 EXT2.19@2.51,15.31 EXT2.19@2.51,17.85 EXT2.19@2.51,20.39 EXT2.19@2.51,22.93 EXT2.19@2.51,25.47 EXT2.19@2.51,28.01 EXT2.19@2.51,30.55 EXT2.19@2.51,33.09 EXT2.19@2.51,35.63 EXT2.19@5.05,12.77 EXT2.19@5.05,15.31 EXT2.19@5.05,17.85 EXT2.19@5.05,20.39 EXT2.19@5.05,22.93 EXT2.19@5.05,25.47 EXT2.19@5.05,28.01 EXT2.19@5.05,30.55 EXT2.19@5.05,33.09 EXT2.19@5.05,35.63 EXT3.5 EXT3.6 EXT3.13 EXT3.14 EXT3.15 EXT3.16 EXT3.17 EXT3.18 EXT3.19@21.071,77.819 EXT3.19@21.071,80.359 EXT3.19@23.611,77.819 EXT3.19@23.611,80.359 EXT3.19@26.151,77.819 EXT3.19@26.151,80.359 EXT3.19@28.691,77.819 EXT3.19@28.691,80.359 EXT3.19@31.231,77.819 EXT3.19@31.231,80.359 EXT3.19@33.771,77.819 EXT3.19@33.771,80.359 EXT3.19@36.311,77.819 EXT3.19@36.311,80.359 EXT3.19@38.851,77.819 EXT3.19@38.851,80.359 EXT3.19@41.391,77.819 EXT3.19@41.391,80.359 EXT3.19@43.931,77.819 EXT3.19@43.931,80.359 U100.1 U100.2 U100.3 U100.6 U100.7 U101.7 U101.10 U101.15 U101.16 U101.17 U101.18 U101.19 U101.20

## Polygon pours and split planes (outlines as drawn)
GND on Bottom Layer "GND" (hatched 45Degree grid 0.5 track 0.2, remove dead copper, pour order 30): 10.248,24.084 10.248,12.07 61.499,12.07 61.468,12.101 61.468,24.084
GND on Bottom Layer "GND" (hatched 45Degree grid 0.5 track 0.2, pour order 28): 15.002,53.322 15.002,40.665 57.836,40.665 57.836,53.254
GND on Bottom Layer "GND" (hatched 45Degree grid 0.5 track 0.2, pour order 26): 15.002,52.837 15.011,52.827 15.011,40.665
GND on Bottom Layer "GND" (solid, remove dead copper, pour order 6): 0,0 65,0 65,84 0.001,84
GND on Top Layer "GND" (solid, remove dead copper, pour order 4): 0,0 65,0 65,84 0.001,84

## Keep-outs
Keep-Out Layer:
  lines w0.1: 64.732,0.24 0.252,0.24 0.252,22.743 0.25,22.745 -6.225,22.745 -6.225,25.695 0.25,25.695 ; 64.748,0.24 64.748,83.751 ; 0.25,25.695 0.25,25.695 ; 0.25,25.695 0.25,41.639 0.25,58.32 ; 0.25,58.32 0.25,58.32 ; 0.25,58.32 -6.2,58.32 -6.2,61.22 0.225,61.22 0.25,61.245 0.25,83.749 31.024,83.749 31.026,83.751 31.026,88.975 33.976,88.975 33.976,83.751 ; 33.976,83.751 49.92,83.751 64.748,83.751 ; 33.976,83.751 33.976,83.751 ; 64.748,83.751 64.748,83.751

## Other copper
Top Layer:
  pour cut-out: 10.248,24.084 10.248,12.603 10.248,12.07 10.781,12.07 22.491,12.07 22.491,24.008 22.491,24.084 22.415,24.084
  pour cut-out: 21.627,52.837 15.002,52.837 15.002,40.899 57.081,40.899 57.081,52.769
  pour cut-out: 23.248,24.084 23.248,12.603 23.248,12.07 23.781,12.07 35.491,12.07 35.491,24.008 35.491,24.084 35.415,24.084
  pour cut-out: 36.248,24.084 36.248,12.603 36.248,12.07 36.781,12.07 48.491,12.07 48.491,24.008 48.491,24.084 48.415,24.084
  pour cut-out: 49.256,24.084 49.256,12.603 49.256,12.07 49.79,12.07 61.499,12.07 61.499,24.008 61.499,24.084 61.423,24.084
  region net X_1: 15.812,41.207 16.312,41.207 16.312,41.707 23.812,41.707 23.812,42.207 16.312,42.207 16.312,43.827 23.252,43.827 23.252,44.327 16.312,44.327 16.312,45.957 23.252,45.957 23.252,46.457 16.312,46.457 16.312,48.087 23.252,48.087 23.252,48.587 16.312,48.587 16.312,50.207 23.252,50.207 23.252,50.707 16.312,50.707 15.812,50.707
  region net X_2: 29.812,42.207 29.812,43.827 24.872,43.827 24.872,44.327 29.812,44.327 29.812,45.957 24.872,45.957 24.872,46.457 29.812,46.457 29.812,48.087 24.872,48.087 24.872,48.587 29.812,48.587 29.812,50.207 24.872,50.207 24.872,50.707 29.812,50.707 30.312,50.707 35.252,50.707 35.252,50.207 30.312,50.207 30.312,48.587 35.252,48.587 35.252,48.087 30.312,48.087 30.312,46.457 35.252,46.457 35.252,45.957 30.312,45.957 30.312,44.327 35.252,44.327 35.252,43.827 30.312,43.827 30.312,42.207 35.812,42.207 35.812,41.707 30.312,41.707 30.312,41.207 29.812,41.207 29.812,41.707 24.312,41.707 24.312,42.207 29.812,42.207
  region net X_3: 41.812,42.207 41.812,43.827 36.872,43.827 36.872,44.327 41.812,44.327 41.812,45.957 36.872,45.957 36.872,46.457 41.812,46.457 41.812,48.087 36.872,48.087 36.872,48.587 41.812,48.587 41.812,50.207 36.872,50.207 36.872,50.707 41.812,50.707 42.312,50.707 47.252,50.707 47.252,50.207 42.312,50.207 42.312,48.587 47.252,48.587 47.252,48.087 42.312,48.087 42.312,46.457 47.252,46.457 47.252,45.957 42.312,45.957 42.312,44.327 47.252,44.327 47.252,43.827 42.312,43.827 42.312,42.207 47.812,42.207 47.812,41.707 42.312,41.707 42.312,41.207 41.812,41.207 41.812,41.707 36.312,41.707 36.312,42.207 41.812,42.207
  region net X_4: 56.312,41.207 55.812,41.207 55.812,41.707 48.312,41.707 48.312,42.207 55.812,42.207 55.812,43.827 48.872,43.827 48.872,44.327 55.812,44.327 55.812,45.957 48.872,45.957 48.872,46.457 55.812,46.457 55.812,48.087 48.872,48.087 48.872,48.587 55.812,48.587 55.812,50.207 48.872,50.207 48.872,50.707 55.812,50.707 56.312,50.707
  region net Y_1: 15.812,51.707 15.812,51.207 23.812,51.207 23.812,49.587 16.872,49.587 16.872,49.087 23.812,49.087 23.812,47.457 16.872,47.457 16.872,46.957 23.812,46.957 23.812,45.327 16.872,45.327 16.872,44.827 23.812,44.827 23.812,43.207 16.872,43.207 16.872,42.707 23.812,42.707 24.312,42.707 29.252,42.707 29.252,43.207 24.312,43.207 24.312,44.827 29.252,44.827 29.252,45.327 24.312,45.327 24.312,46.957 29.252,46.957 29.252,47.457 24.312,47.457 24.312,49.087 29.252,49.087 29.252,49.587 24.312,49.587 24.312,51.207 30.312,51.207 35.812,51.207 35.812,49.587 30.872,49.587 30.872,49.087 35.812,49.087 35.812,47.457 30.872,47.457 30.872,46.957 35.812,46.957 35.812,45.327 30.872,45.327 30.872,44.827 35.812,44.827 35.812,43.207 30.872,43.207 30.872,42.707 35.812,42.707 36.312,42.707 41.252,42.707 41.252,43.207 36.312,43.207 36.312,44.827 41.252,44.827 41.252,45.327 36.312,45.327 36.312,46.957 41.252,46.957 41.252,47.457 36.312,47.457 36.312,49.087 41.252,49.087 41.252,49.587 36.312,49.587 36.312,51.207 42.312,51.207 47.812,51.207 47.812,49.587 42.872,49.587 42.872,49.087 47.812,49.087 47.812,47.457 42.872,47.457 42.872,46.957 47.812,46.957 47.812,45.327 42.872,45.327 42.872,44.827 47.812,44.827 47.812,43.207 42.872,43.207 42.872,42.707 47.812,42.707 48.312,42.707 55.252,42.707 55.252,43.207 48.312,43.207 48.312,44.827 55.252,44.827 55.252,45.327 48.312,45.327 48.312,46.957 55.252,46.957 55.252,47.457 48.312,47.457 48.312,49.087 55.252,49.087 55.252,49.587 48.312,49.587 48.312,51.207 56.312,51.207 56.312,51.707
Bottom Layer:
  pour cut-out: 11.905,41.986 11.905,35.494 12.472,34.927 15.681,38.136 15.681,40.96 15.002,41.639
  pour cut-out: 21.627,52.837 15.002,52.837 15.002,40.899 57.081,40.899 57.081,52.769
  pour cut-out: 10.248,24.084 10.248,12.603 10.248,12.07 10.781,12.07 61.468,12.07 61.468,24.084 22.415,24.084

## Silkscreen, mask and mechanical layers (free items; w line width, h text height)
Top Overlay:
  lines w0.1: 0.3,11.266 6.34,11.266 6.34,36.584 ; 0.3,37.174 5.75,37.174 ; 0.3,46.826 6.34,46.826 6.34,72.144 5.75,72.734 0.3,72.734
Bottom Overlay:
  text "EXT3" at 34.701,82.097 h2
  text "2" at 46.352,79.929 h2 r270
  text "1" at 46.237,77.097 h2 r270
  text "SCL" at 30.609,73.6 h1.52 r270
  text "VCC" at 20.497,73.402 h1.52 r270
  text "2" at 1.732,72.998 h2
  text "GND" at 43.688,72.871 h1.52 r270
  text "1" at 7.413,72.842 h2
  text "Y1" at 40.996,70.917 h1.52 r270
  text "X1" at 35.992,70.866 h1.52 r270
  text "Y2" at 39.649,70.815 h1.52 r270
  text "X4" at 31.928,70.79 h1.52 r270
  text "X3" at 33.376,70.79 h1.52 r270
  text "X2" at 34.747,70.714 h1.52 r270
  text "GND" at 10.439,70.674 h1.52
  text "ID_DATA" at 17.17,70.674 h1.52
  text "SDA" at 30.558,70.272 h1.52 r270
  text "GND" at 20.472,69.745 h1.52 r270
  text "Y1" at 12.42,69.291 h1.52
  text "ID_DATA" at 43.675,66.836 h1.52 r270
  text "Y2" at 12.268,64.785 h1.52
  text "SCL" at 9.652,57.963 h1.52
  text "SDA" at 12.979,57.912 h1.52
  text "VCC" at 9.487,47.776 h1.52
  text "GND" at 13.144,47.751 h1.52
  text "EXT1" at 6.042,43.172 h2
  text "M" at 45.902,39.662 h10
  text "2" at 2.997,37.537 h2
  text "1" at 5.527,37.537 h2
  text "GND" at 9.779,35.789 h1.52
  text "NC" at 12.065,35.738 h1.52
  text "T10" at 46.254,35.389 h2
  text "PRO" at 29.454,35.38 h1
  text "PLAINED" at 38.519,35.365 h2
  text "X" at 41.919,35.365 h4
  text "X1" at 12.192,34.087 h1.52
  text "X2" at 12.217,32.563 h1.52
  text "X3" at 12.243,31.119 h1.52
  text "X4" at 12.243,29.864 h1.52
  text "A08-3059 Rev 1" at 41.969,17.537 h2
  text "VCC" at 9.487,12.216 h1.52
  text "GND" at 13.144,12.191 h1.52
  text "Microchip © 2019" at 45.853,11.439 h2
  text "EXT2" at 5.987,7.867 h2
  text "p" at 41.339,3.237 h8
  text "c" at 52.236,3.185 h7.5
  text "e" at 32.81,2.869 h8
  text "" at 21.966,-0.448 h12
Mechanical 1:
  lines w0.1: 0,61.53 -6.5,61.53 -6.5,58.03 0,58.03 0,25.97 -6.5,25.97 -6.5,22.47 0,22.47 0,0 65,0 65,84 34.251,84 ; 0.001,61.531 0.001,84 30.751,84 ; 30.751,84.001 30.751,89.254 34.251,89.254 34.251,84.001
Mechanical 4:
  text "Extension Connector 1" at 5.35,50.765 h1 r90
  text "Extension Connector 2" at 5.425,15.49 h1 r90
Mechanical 13:
  circle w0.254: c53.15,30.021 r1
Mechanical 16:
  lines w0.127: -159,-57.695 -153.92,-57.695 ; -159,12.965 -153.92,12.965 ; -159,83.45 -153.92,83.45 ; -109.724,-128.18 -109.724,-123.1 ; -109.724,148.68 -109.724,153.76 ; -65.7,148.68 -65.7,153.76 ; -60.575,-128.18 -60.575,-123.1 ; -16.525,148.68 -16.525,153.76 ; -11.426,-128.18 -11.426,-123.1 ; 37.85,-128.18 37.85,-123.1 ; 37.85,148.68 37.85,153.76 ; 86.999,-128.18 86.999,-123.1 ; 86.999,148.68 86.999,153.76 ; 115.32,-115.48 229.62,-115.48 ; 115.32,-107.86 229.62,-107.86 ; 115.32,-100.24 153.42,-100.24 ; 136.148,-128.18 136.148,-123.1 ; 136.148,148.68 136.148,153.76 ; 153.42,-123.1 153.42,-107.86 153.42,-92.62 ; 185.424,-128.18 185.424,-123.1 ; 185.424,148.68 185.424,153.76 ; 206.76,-123.1 206.76,-107.86 ; 229.62,-57.695 234.7,-57.695 ; 229.62,12.92 234.7,12.92 ; 229.62,83.405 234.7,83.405 ; 115.32,-123.1 115.32,-92.62 ; 115.32,-123.1 229.62,-123.1 ; 115.32,-123.1 79.76,-123.1 79.76,-92.62 115.32,-92.62 ; 115.32,-92.62 153.42,-92.62 ; 153.42,-92.62 229.62,-92.62 229.62,-123.1 ; 229.62,-123.1 229.62,148.68 -153.92,148.68 -153.92,-123.1 229.62,-123.1 ; -159,-128.18 234.7,-128.18 234.7,153.76 -159,153.76 -159,-128.18
  text "1" at -134.963,150.331 h0.67
  text "4" at 12.628,150.331 h0.67
  text "5" at 61.904,150.331 h0.67
  text "6" at 110.926,150.331 h0.67
  text "7" at 160.456,150.331 h0.67
  text "8" at 209.478,150.331 h0.67
  text "2" at -88.474,150.195 h0.67
  text "3" at -41.924,150.045 h0.67
  text "A" at -157.095,116.521 h0.67
  text "A" at 231.525,116.476 h0.67
  text "B" at 231.605,48.421 h0.67
  text "B" at -157.095,45.909 h0.67
  text "C" at -157.188,-22.268 h0.67
  text "C" at 231.975,-27.88 h0.67
  text "D" at -157.095,-94.982 h0.67
  text "D" at 231.525,-94.982 h0.67
  text "TITLE:" at 154.69,-95.16 h0.67
  text "PCB DESIGNER:" at 116.59,-102.653 h0.67
  text "PART NO.:" at 154.69,-110.4 h0.67
  text "REV:" at 208.03,-110.4 h0.67
  text ".PRINT_DATE" at 116.7,-114.28 h0.67
  text "Vestre Rosten 79" at 83.97,-117.258 h0.67
  text "FILE NAME:" at 116.59,-118.02 h0.67
  text "DWG NO:" at 154.69,-118.02 h0.67
  text "SCALE:" at 208.03,-118.02 h0.67
  text "N-7075 Tiller" at 83.97,-120.56 h0.67
  text ".PCB_FILE_NAME_NO_PATH" at 117.86,-121.068 h0.67
  text "2" at -85.34,-126.468 h0.67
  text "3" at -35.81,-126.468 h0.67
  text "4" at 13.212,-126.468 h0.67
  text "5" at 61.904,-126.468 h0.67
  text "6" at 110.926,-126.468 h0.67
  text "7" at 160.456,-126.468 h0.67
  text "8" at 209.478,-126.468 h0.67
